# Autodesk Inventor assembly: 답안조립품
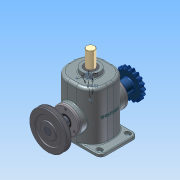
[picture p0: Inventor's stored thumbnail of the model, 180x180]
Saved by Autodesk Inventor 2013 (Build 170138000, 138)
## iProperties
Created: 2014-12
Part Number: 답안조립품
Document SubType Name: Assembly
Designer: Administrator
Mass: 8252.43 g
Surface Area: 4222.88 cm^2
Volume: 1869.04 cm^3
Density: 4.41532 g/cm^3
Author: Administrator
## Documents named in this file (15)
- C:\Users\Administrator\Desktop\341209V1023\341209V1023\답안조립품.iam
- C:\Users\Administrator\Desktop\341209V1023\341209V1023\본체.ipt
- C:\Users\Administrator\Desktop\341209V1023\341209V1023\편심축.ipt
- C:\Users\Administrator\Desktop\341209V1023\341209V1023\V-벨트풀리.ipt
- C:\Users\Administrator\Desktop\341209V1023\341209V1023\체인 스프로킷.ipt
- C:\Users\Administrator\Desktop\341209V1023\341209V1023\커버.ipt
- C:\Users\Administrator\Desktop\341209V1023\341209V1023\슬라이드.ipt
- C:\Users\Administrator\Desktop\341209V1023\341209V1023\가변스프링.ipt
- C:\Users\Administrator\Desktop\341209V1023\341209V1023\베어링 6205.ipt
- C:\Users\Administrator\Desktop\341209V1023\341209V1023\오일실.ipt
- C:\Users\Administrator\Desktop\341209V1023\341209V1023\부시.ipt
- C:\Users\Administrator\Desktop\341209V1023\341209V1023\키 8x8.ipt
- C:\Users\Administrator\Desktop\341209V1023\341209V1023\멈춤링.ipt
- C:\Users\Administrator\Desktop\341209V1023\341209V1023\M4x0.5.ipt
- C:\Users\Administrator\Desktop\341209V1023\341209V1023\멈춤나사 M5x0.5.ipt
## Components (9 placed, 4 different names)
1. V-벨트풀리:1
2. 5-체인 스프로킷:1
3. 가변스프링:1
4. M4x0.5:1
5. M4x0.5:2
6. M4x0.5:3
7. M4x0.5:4
8. M4x0.5:5
9. M4x0.5:6
